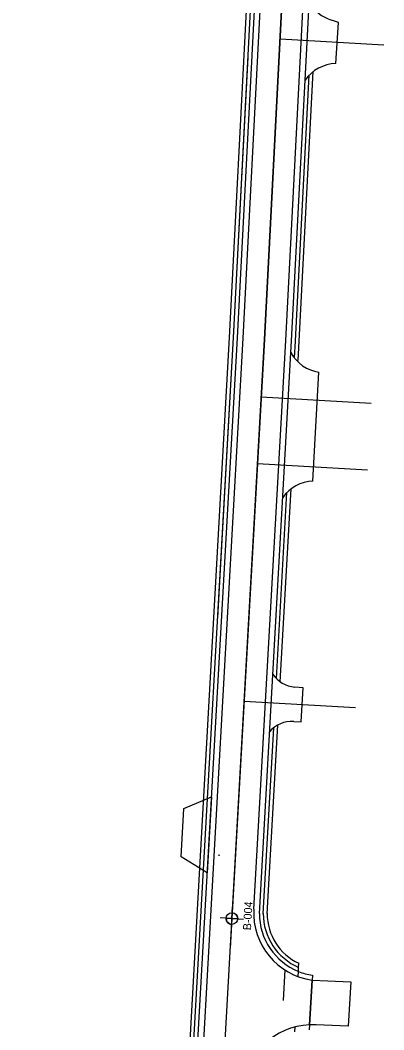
# Model space of a CAD drawing. Extents: x 1973866 to 1974130, y 734965 to 738427.
# Drawn here: x 1973884 to 1974072, y 736854 to 737376 of the extents above; entities that cross this region are included whole.
import ezdxf

# ---------------------------------------------------------------- set-up
doc = ezdxf.new("R2010")
doc.units = 0
for name, color, linetype in [('_CIVIL_CONSTRUCTION', 7, 'Continuous'), ('CM_Corridor_Range_Conceptual', 7, 'Continuous'), ('DR_P_Cells', 7, 'Continuous'), ('DR_P_Headwall', 7, 'Continuous'), ('DR_P_Storm_Sewer', 7, 'Continuous'), ('DR_X_Cells', 7, 'Continuous'), ('DR_X_Storm_Sewer', 7, 'Continuous'), ('GK_Drainage_Nodes', 7, 'Continuous'), ('MD_P_ACIC_B', 7, 'Continuous'), ('MD_P_Surface_Asphalt_Concrete_Base', 7, 'Continuous'), ('PF_X_Ground_Line', 7, 'Continuous'), ('PV_P_Shoulder', 7, 'Continuous'), ('SC_ProfileRun2', 7, 'Continuous'), ('SC_ProfileRun3', 7, 'Continuous'), ('SC_Scratch1', 7, 'Continuous'), ('SH_Text', 7, 'Continuous')]:
    doc.layers.add(name, color=color, linetype=linetype)

msp = doc.modelspace()

# ---------------------------------------------------------------- linework, layer by layer
at = {"layer": '_CIVIL_CONSTRUCTION'}
for p, q in [((1974048.68, 737374.95), (1974045.06, 737376.08)), ((1974047.19, 737353.66), (1974048.68, 737374.95)), ((1974035.39, 737137.95), (1974038.55, 737194.14)), ((1974030.37, 737031.16), (1974026.02, 737031.51)), ((1974029.37, 737013.44), (1974030.37, 737031.16)), ((1974025.52, 737013.69), (1974029.37, 737013.44)), ((1973968.77, 736968.76), (1973983.13, 736974.7)), ((1973967.37, 736943.76), (1973968.77, 736968.76)), ((1973980.93, 736935.44), (1973967.37, 736943.76))]:
    msp.add_line(p, q, dxfattribs=at)
for centre, radius, start, end in [((1974051.02, 737395.17), 20, 208.814, 252.6777), ((1974047.82, 737333.67), 20, 91.8272, 145.2374), ((1974041.6, 737213.91), 20, 208.6769, 261.2316), ((1974036.24, 737117.97), 20, 92.4278, 145.0009), ((1974027.22, 737046.46), 15, 213.6591, 265.4279), ((1974024.54, 736998.72), 15, 86.2628, 139.9193)]:
    msp.add_arc(centre, radius, start, end, dxfattribs=at)
at = {"layer": 'CM_Corridor_Range_Conceptual'}
for p, q in [((1973992.44, 737212.09), (1974006.34, 737479.55)), ((1974027.87, 737200.25), (1974035.63, 737349.52)), ((1973948.38, 736426.66), (1973992.44, 737212.16)), ((1974018.52, 737034.24), (1974024.11, 737133.87)), ((1974011.79, 736914.24), (1974017.26, 737011.84)), ((1974028.06, 736886.63), (1974028.18, 736888.77))]:
    msp.add_line(p, q, dxfattribs=at)
msp.add_arc((1974040.09, 736914.44), 28.3, 179.9489, 245.1044, dxfattribs=at)
at = {"layer": 'DR_P_Cells'}
for p, q in [((1974010.42, 737211.15), (1974024.31, 737478.61)), ((1973884.41, 734964.92), (1974010.42, 737211.15))]:
    msp.add_line(p, q, dxfattribs=at)
at = {"layer": 'DR_P_Headwall'}
for p, q in [((1974071.97, 737363.22), (1974018.47, 737366.22)), ((1974065.44, 737178.08), (1974008.74, 737181.26)), ((1974063.51, 737143.62), (1974006.81, 737146.8)), ((1974057.41, 737020.74), (1973999.92, 737023.96))]:
    msp.add_line(p, q, dxfattribs=at)
at = {"layer": 'DR_P_Storm_Sewer'}
for p, q in [((1973996.44, 737211.88), (1974010.33, 737479.34)), ((1974024.4, 737210.43), (1974038.29, 737477.89)), ((1973918.64, 735825.07), (1973996.44, 737211.94)), ((1974007.79, 736914.47), (1974024.39, 737210.37))]:
    msp.add_line(p, q, dxfattribs=at)
msp.add_arc((1974040.09, 736914.44), 32.3, 179.9489, 247.8919, dxfattribs=at)
at = {"layer": 'DR_X_Cells'}
for p, q in [((1973994.44, 737211.98), (1974008.33, 737479.44)), ((1974026.39, 737210.32), (1974033.53, 737347.66)), ((1973950.51, 736428.89), (1973994.44, 737212.05)), ((1974025.9, 737201.52), (1974026.39, 737210.26)), ((1974016.61, 737035.86), (1974022, 737132.02)), ((1974009.79, 736914.35), (1974015.18, 737010.45)), ((1974027.94, 736884.51), (1974028.06, 736886.63))]:
    msp.add_line(p, q, dxfattribs=at)
msp.add_arc((1974040.09, 736914.44), 30.3, 179.9489, 246.5963, dxfattribs=at)
at = {"layer": 'DR_X_Storm_Sewer'}
for p, q in [((1974024.31, 737478.61), (1974010.42, 737211.15)), ((1974010.42, 737211.15), (1973992.76, 736896.5))]:
    msp.add_line(p, q, dxfattribs=at)
at = {"layer": 'GK_Drainage_Nodes'}
for p, q in [((1974027.79, 736881.89), (1974027.94, 736884.51)), ((1974035.17, 736882.58), (1974035.03, 736880.08)), ((1974026.15, 736853.25), (1974026.3, 736855.87)), ((1974033.7, 736856.87), (1974033.56, 736854.37))]:
    msp.add_line(p, q, dxfattribs=at)
msp.add_arc((1974039.86, 736914.75), 32.5, 248.478, 261.7033, dxfattribs=at)
at = {"layer": 'MD_P_ACIC_B'}
msp.add_circle((1973993.63, 736911.86), 0.05, dxfattribs=at)
at = {"layer": 'MD_P_Surface_Asphalt_Concrete_Base'}
for p, q in [((1973993.63, 736911.86), (1973993.96, 736917.85)), ((1973993.63, 736911.86), (1973987.64, 736912.19)), ((1973993.63, 736911.86), (1973993.79, 736914.85)), ((1973990.63, 736912.03), (1973993.63, 736911.86)), ((1973993.63, 736911.86), (1973993.29, 736905.87)), ((1973993.63, 736911.86), (1973993.46, 736908.86)), ((1973993.63, 736911.86), (1973999.62, 736911.52)), ((1973996.62, 736911.69), (1973993.63, 736911.86))]:
    msp.add_line(p, q, dxfattribs=at)
msp.add_circle((1973993.63, 736911.86), 3, dxfattribs=at)
for start, end in [(356.7892, 86.7892), (176.7892, 266.7892)]:
    msp.add_arc((1973993.63, 736911.86), 3, start, end, dxfattribs=at)
at = {"layer": 'PF_X_Ground_Line'}
msp.add_lwpolyline([(1973980.93, 736935.44), (1973967.37, 736943.76), (1973968.77, 736968.76), (1973983.13, 736974.7)], close=True, dxfattribs=at)
at = {"layer": 'PV_P_Shoulder'}
for p, q in [((1973994.44, 737212.05), (1974001.97, 737357.02)), ((1973986.33, 737067.51), (1973994.44, 737212.05))]:
    msp.add_line(p, q, dxfattribs=at)
at = {"layer": 'SC_ProfileRun2'}
msp.add_line((1974020.94, 736885.3), (1974020.05, 736869.57), dxfattribs=at)
at = {"layer": 'SC_ProfileRun3'}
msp.add_line((1973987.44, 736944.48), (1973986.45, 736944.53), dxfattribs=at)
at = {"layer": 'SC_Scratch1'}
for p, q in [((1973999.43, 737211.72), (1974013.33, 737479.18)), ((1974021.4, 737210.58), (1974035.3, 737478.04)), ((1973921.63, 735824.9), (1973999.43, 737211.77)), ((1974004.91, 736916.64), (1974021.4, 737210.54)), ((1974035.03, 736880.08), (1974033.7, 736856.87))]:
    msp.add_line(p, q, dxfattribs=at)
for centre, start, end in [((1974039.86, 736914.75), 176.7892, 262.0633), ((1974034.65, 736821.88), 91.5535, 176.7892)]:
    msp.add_arc(centre, 35, start, end, dxfattribs=at)
at = {"layer": 'SH_Text'}
msp.add_lwpolyline([(1974043.12, 736879.61), (1974054.97, 736879.11), (1974053.67, 736856.26), (1974037.06, 736856.86), (1974033.7, 736856.87), (1974035.03, 736880.08)], close=True, dxfattribs=at)

# ---------------------------------------------------------------- texts
at = {"layer": 'SC_Scratch1'}
msp.add_text('B-004', height=4.167, rotation=86.7892, dxfattribs=at).set_placement((1974003.46, 736905.71))

doc.saveas('drawing.dxf')
